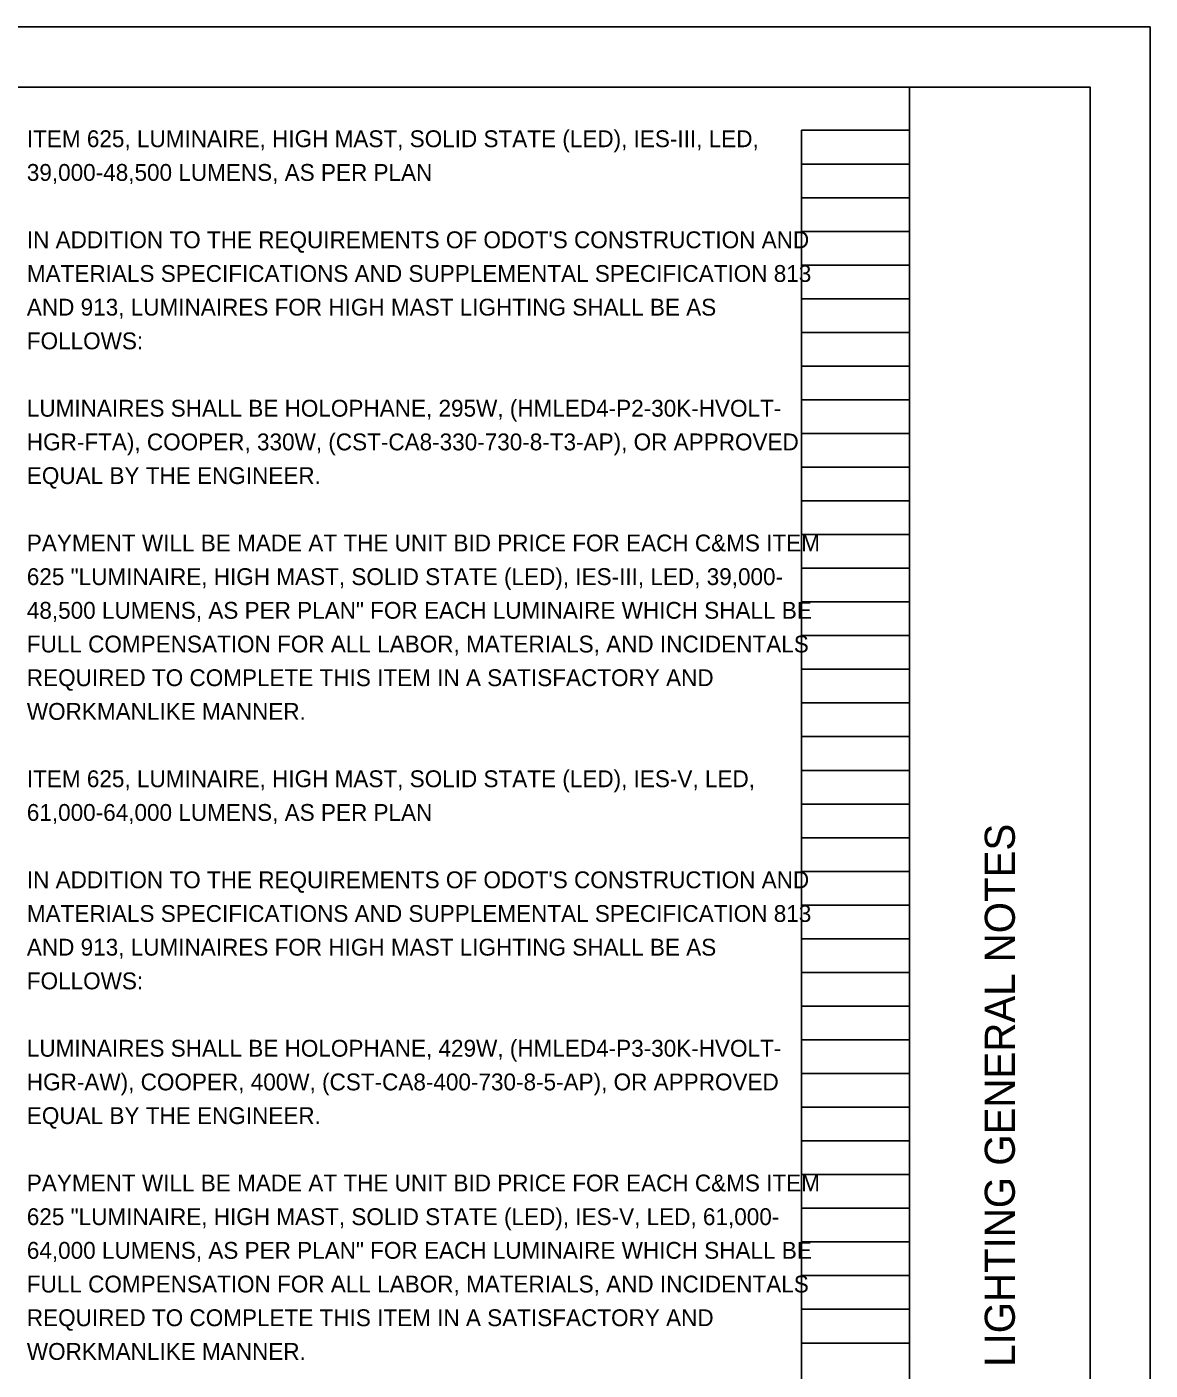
# Model space of a CAD drawing. Extents: x 0 to 49.8, y -1.8 to 22.
# Drawn here: x 24.66 to 34, y 10.83 to 22 of the extents above; entities that cross this region are included whole.
import ezdxf

# ---------------------------------------------------------------- set-up
doc = ezdxf.new("R2010")
doc.units = 0
for name, color, linetype in [('SH_Border', 7, 'Continuous'), ('SH_Cut_Line', 7, 'Continuous'), ('SH_Data', 7, 'Continuous'), ('SH_Text', 7, 'Continuous')]:
    doc.layers.add(name, color=color, linetype=linetype)

msp = doc.modelspace()

# ---------------------------------------------------------------- linework, layer by layer
at = {"layer": 'SH_Border'}
msp.add_line((32, 0.5), (32, 21.5), dxfattribs=at)
msp.add_lwpolyline([(1.5, 21.5), (33.5, 21.5), (33.5, 0.5), (1.5, 0.5)], close=True, dxfattribs=at)
at = {"layer": 'SH_Cut_Line'}
msp.add_lwpolyline([(0, 0), (34, 0), (34, 22), (0, 22)], close=True, dxfattribs=at)
at = {"layer": 'SH_Data'}
for p, q in [((31.1, 0.98), (31.1, 21.14)), ((31.1, 21.14), (32, 21.14)), ((32, 0.98), (32, 21.14)), ((31.1, 20.86), (32, 20.86)), ((31.1, 20.58), (32, 20.58)), ((31.1, 20.3), (32, 20.3)), ((31.1, 20.02), (32, 20.02)), ((31.1, 19.74), (32, 19.74)), ((31.1, 19.46), (32, 19.46)), ((31.1, 19.18), (32, 19.18)), ((31.1, 18.9), (32, 18.9)), ((31.1, 18.62), (32, 18.62)), ((31.1, 18.34), (32, 18.34)), ((31.1, 18.06), (32, 18.06)), ((31.1, 17.78), (32, 17.78)), ((31.1, 17.5), (32, 17.5)), ((31.1, 17.22), (32, 17.22)), ((31.1, 16.94), (32, 16.94)), ((31.1, 16.66), (32, 16.66)), ((31.1, 16.38), (32, 16.38)), ((31.1, 16.1), (32, 16.1)), ((31.1, 15.82), (32, 15.82)), ((31.1, 15.54), (32, 15.54)), ((31.1, 15.26), (32, 15.26)), ((31.1, 14.98), (32, 14.98)), ((31.1, 14.7), (32, 14.7)), ((31.1, 14.42), (32, 14.42)), ((31.1, 14.14), (32, 14.14)), ((31.1, 13.86), (32, 13.86)), ((31.1, 13.58), (32, 13.58)), ((31.1, 13.3), (32, 13.3)), ((31.1, 13.02), (32, 13.02)), ((31.1, 12.74), (32, 12.74)), ((31.1, 12.46), (32, 12.46)), ((31.1, 12.18), (32, 12.18)), ((31.1, 11.9), (32, 11.9)), ((31.1, 11.62), (32, 11.62)), ((31.1, 11.34), (32, 11.34)), ((31.1, 11.06), (32, 11.06))]:
    msp.add_line(p, q, dxfattribs=at)

# ---------------------------------------------------------------- texts
msp.add_text('LIGHTING GENERAL NOTES', height=0.25, rotation=90, dxfattribs=at).set_placement((32.875, 10.862))
at = {"layer": 'SH_Text'}
for s, p in [('ITEM 625, LUMINAIRE, HIGH MAST, SOLID STATE (LED), IES-III, LED, ', (24.66, 21)), ('39,000-48,500 LUMENS, AS PER PLAN', (24.66, 20.72)), ("IN ADDITION TO THE REQUIREMENTS OF ODOT'S CONSTRUCTION AND ", (24.66, 20.16)), ('MATERIALS SPECIFICATIONS AND SUPPLEMENTAL SPECIFICATION 813 ', (24.66, 19.88)), ('AND 913, LUMINAIRES FOR HIGH MAST LIGHTING SHALL BE AS ', (24.66, 19.6)), ('FOLLOWS:', (24.66, 19.32)), ('LUMINAIRES SHALL BE HOLOPHANE, 295W, (HMLED4-P2-30K-HVOLT-', (24.66, 18.76)), ('HGR-FTA), COOPER, 330W, (CST-CA8-330-730-8-T3-AP), OR APPROVED ', (24.66, 18.48)), ('EQUAL BY THE ENGINEER.', (24.66, 18.2)), ('PAYMENT WILL BE MADE AT THE UNIT BID PRICE FOR EACH C&MS ITEM ', (24.66, 17.64)), ('625 "LUMINAIRE, HIGH MAST, SOLID STATE (LED), IES-III, LED, 39,000-', (24.66, 17.36)), ('48,500 LUMENS, AS PER PLAN" FOR EACH LUMINAIRE WHICH SHALL BE ', (24.66, 17.08)), ('FULL COMPENSATION FOR ALL LABOR, MATERIALS, AND INCIDENTALS ', (24.66, 16.8)), ('REQUIRED TO COMPLETE THIS ITEM IN A SATISFACTORY AND ', (24.66, 16.52)), ('WORKMANLIKE MANNER.', (24.66, 16.24)), ('ITEM 625, LUMINAIRE, HIGH MAST, SOLID STATE (LED), IES-V, LED, ', (24.66, 15.68)), ('61,000-64,000 LUMENS, AS PER PLAN', (24.66, 15.4)), ("IN ADDITION TO THE REQUIREMENTS OF ODOT'S CONSTRUCTION AND ", (24.66, 14.84)), ('MATERIALS SPECIFICATIONS AND SUPPLEMENTAL SPECIFICATION 813 ', (24.66, 14.56)), ('AND 913, LUMINAIRES FOR HIGH MAST LIGHTING SHALL BE AS ', (24.66, 14.28)), ('FOLLOWS:', (24.66, 14)), ('LUMINAIRES SHALL BE HOLOPHANE, 429W, (HMLED4-P3-30K-HVOLT-', (24.66, 13.44)), ('HGR-AW), COOPER, 400W, (CST-CA8-400-730-8-5-AP), OR APPROVED ', (24.66, 13.16)), ('EQUAL BY THE ENGINEER.', (24.66, 12.88)), ('PAYMENT WILL BE MADE AT THE UNIT BID PRICE FOR EACH C&MS ITEM ', (24.66, 12.32)), ('625 "LUMINAIRE, HIGH MAST, SOLID STATE (LED), IES-V, LED, 61,000-', (24.66, 12.04)), ('64,000 LUMENS, AS PER PLAN" FOR EACH LUMINAIRE WHICH SHALL BE ', (24.66, 11.76)), ('FULL COMPENSATION FOR ALL LABOR, MATERIALS, AND INCIDENTALS ', (24.66, 11.48)), ('REQUIRED TO COMPLETE THIS ITEM IN A SATISFACTORY AND ', (24.66, 11.2)), ('WORKMANLIKE MANNER.', (24.66, 10.92))]:
    msp.add_text(s, height=0.14, dxfattribs=at).set_placement(p)

doc.saveas('drawing.dxf')
